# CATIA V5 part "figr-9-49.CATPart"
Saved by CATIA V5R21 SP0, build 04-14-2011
Part number: Part1
Bounding box of the stored display mesh (mm): x -53.48 to 62.241, y -50 to 50, z -57.709 to 133.109
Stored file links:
  D:\CATIA V5R21 E-RESOURCES\CATIA-V5R21\catia-v5r21-prt\c09-catia-v5r20-prt\c09-catia-v5r21-figr-9-49.CATPart
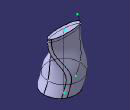
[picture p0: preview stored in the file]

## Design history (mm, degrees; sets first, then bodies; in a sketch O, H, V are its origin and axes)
Body1 (main body)
  Plane1: type Offset, RefPlane xy-plane, Offset 103
  Sketch1 on Plane1, origin (0, 0, 103), H (1, 0, 0), V (0, 1, 0)
    ellipse A1 centre (0, 0) semi-axes 50, 13.2069 rotation 0
    point P1 (50, 0)
    "Radius" A1 = 50
    coincidence: P1 H, A1 P1
  Extremum1: Reference Sketch1, Direction (1, 2, 3)
  Sketch2 on xy-plane, origin (0, 0, 0), H (1, 0, 0), V (0, 1, 0)
    circle A1 centre (0, 0) radius 50
    radius A1 = 50
  Extremum2: Reference Sketch2, Direction (1, 2, 3)
  Sketch3 on zx-plane, origin (0, 0, 0), H (-1, 0, 0), V (0, 0, 1)
    spline S1 through (37.7591, -31.0289) (41.8235, -21.251) (50, 0) (49.8084, 85.7657) (50, 103) (41.6255, 133.1089)
    reference projected line E1 (-50, 103) -> (50, 103) from Sketch1.A1
    point P1 (50, 0)
    point P2 (50, 103)
    distance V P1 = 50
    distance P2 V = 50
    coincidence: P1 H, P2 E1
  Sketch4 on zx-plane, origin (0, 0, 0), H (-1, 0, 0), V (0, 0, 1)
    line L1 (0, 111.062) -> (0, -57.7094)
    point P1 (0, 111.062)
    coincidence: P1 V
    vertical: L1 V
  Loft1: solid, Sections (Sketch1; Sketch2), Spine Sketch4, Guides Sketch3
